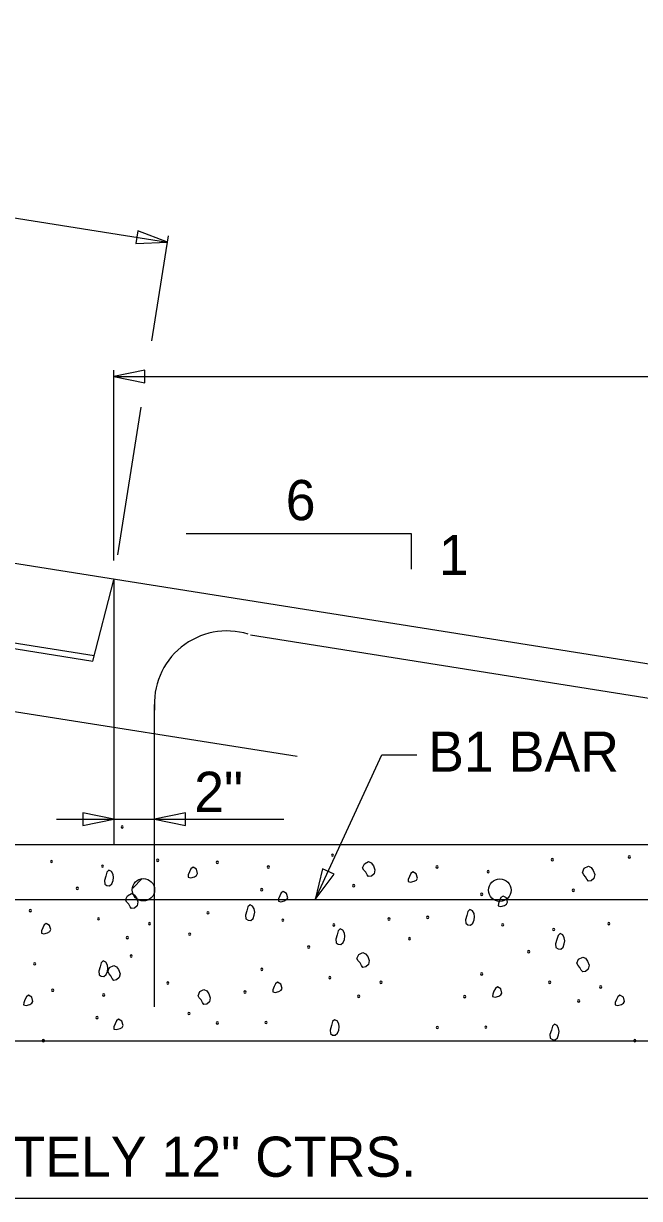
# Model space of a CAD drawing. Extents: x -439.2 to -407.9, y -458.1 to -436.2.
# Drawn here: x -431.521 to -429.218, y -451.117 to -446.728 of the extents above; entities that cross this region are included whole.
import ezdxf

# ---------------------------------------------------------------- set-up
doc = ezdxf.new("R2010")
doc.units = 0
doc.layers.add('Level 4', color=7, linetype='Continuous')
doc.layers.add('Level 45', color=7, linetype='Continuous')

msp = doc.modelspace()

# ---------------------------------------------------------------- linework, layer by layer
at = {"layer": 'Level 4'}
for p, q in [((-436.1395, -446.7284), (-430.9827, -447.5452)), ((-439.1627, -447.54), (-425.6904, -449.6734)), ((-431.0411, -447.9134), (-430.979, -447.5214)), ((-431.1827, -448.7339), (-431.1827, -448.023)), ((-431.1827, -448.0471), (-425.6902, -448.0471)), ((-431.1677, -448.7131), (-431.0803, -448.1614)), ((-436.4193, -448.2716), (-431.2564, -449.0896)), ((-436.4245, -448.2926), (-431.261, -449.11)), ((-436.5705, -448.5037), (-430.4973, -449.4655)), ((-430.9131, -448.6339), (-430.071, -448.6339)), ((-430.071, -448.6339), (-430.071, -448.7672)), ((-431.261, -449.11), (-431.1829, -448.8061)), ((-431.1829, -448.804), (-431.1829, -449.7952)), ((-430.6716, -449.0119), (-426.0033, -449.7521)), ((-431.0317, -449.2723), (-431.0317, -450.401)), ((-430.4303, -450.0011), (-430.1809, -449.4603)), ((-430.1809, -449.4603), (-430.0506, -449.4603)), ((-431.397, -449.7005), (-430.5476, -449.7005)), ((-436.4193, -449.7952), (-425.6904, -449.7952)), ((-431.1122, -449.958), (-431.0767, -449.9225)), ((-436.9348, -450.001), (-431.0317, -450.001)), ((-431.0317, -450.001), (-425.8762, -450.001)), ((-437.1984, -450.5281), (-425.6904, -450.5281)), ((-425.6902, -451.1174), (-437.1989, -451.1174))]:
    msp.add_line(p, q, dxfattribs=at)
for points in [[(-431.1012, -447.5508), (-430.9827, -447.5452), (-431.0937, -447.5032)], [(-431.0666, -448.023), (-431.1827, -448.0471), (-431.0666, -448.0712)], [(-431.2989, -449.7246), (-431.1827, -449.7005), (-431.2989, -449.6764)], [(-430.9153, -449.6764), (-431.0315, -449.7005), (-430.9153, -449.7246)], [(-430.2529, -449.8825), (-430.2463, -449.8668), (-430.2308, -449.8592), (-430.2206, -449.864), (-430.2127, -449.8748), (-430.207, -449.89), (-430.2101, -449.9046), (-430.2201, -449.9135), (-430.2308, -449.915), (-430.2363, -449.9079), (-430.2412, -449.8981), (-430.2482, -449.8905), (-430.2529, -449.8825)], [(-431.2014, -449.891), (-431.2093, -449.8984), (-431.213, -449.913), (-431.2184, -449.9298), (-431.2169, -449.9429), (-431.2087, -449.9485), (-431.1988, -449.9494), (-431.1903, -449.942), (-431.1858, -449.9299), (-431.184, -449.9182), (-431.1858, -449.9066), (-431.1918, -449.8957), (-431.2014, -449.891)], [(-430.8868, -449.8803), (-430.8946, -449.8862), (-430.8998, -449.8972), (-430.9045, -449.9084), (-430.9049, -449.9166), (-430.8955, -449.919), (-430.8816, -449.9154), (-430.8738, -449.9106), (-430.8699, -449.9037), (-430.8741, -449.8877), (-430.8868, -449.8803)], [(-430.4035, -449.8855), (-430.4303, -450.0011), (-430.3597, -449.9057)], [(-430.065, -449.8975), (-430.0727, -449.9034), (-430.0779, -449.9144), (-430.0827, -449.9256), (-430.0831, -449.9339), (-430.0736, -449.9362), (-430.0598, -449.9326), (-430.052, -449.9278), (-430.0481, -449.9209), (-430.0523, -449.9049), (-430.065, -449.8975)], [(-429.4311, -449.8998), (-429.4245, -449.884), (-429.409, -449.8764), (-429.3987, -449.8813), (-429.3909, -449.892), (-429.3851, -449.9072), (-429.3883, -449.9218), (-429.3983, -449.9307), (-429.409, -449.9322), (-429.4145, -449.9252), (-429.4194, -449.9153), (-429.4264, -449.9078), (-429.4311, -449.8998)], [(-431.1388, -450.0021), (-431.1323, -449.9863), (-431.1168, -449.9787), (-431.1065, -449.9836), (-431.0986, -449.9943), (-431.0929, -450.0095), (-431.096, -450.0241), (-431.106, -450.033), (-431.1168, -450.0345), (-431.1222, -450.0275), (-431.1271, -450.0176), (-431.1341, -450.0101), (-431.1388, -450.0021)], [(-430.5497, -449.9703), (-430.5575, -449.9762), (-430.5627, -449.9872), (-430.5675, -449.9984), (-430.5679, -450.0066), (-430.5584, -450.009), (-430.5445, -450.0054), (-430.5368, -450.0006), (-430.5328, -449.9937), (-430.5371, -449.9777), (-430.5497, -449.9703)], [(-429.7279, -449.9875), (-429.7357, -449.9934), (-429.7409, -450.0044), (-429.7456, -450.0156), (-429.7461, -450.0239), (-429.7366, -450.0262), (-429.7227, -450.0226), (-429.7149, -450.0178), (-429.711, -450.0109), (-429.7153, -449.9949), (-429.7279, -449.9875)], [(-430.6736, -450.0204), (-430.6815, -450.0278), (-430.6852, -450.0425), (-430.6905, -450.0593), (-430.6891, -450.0723), (-430.6809, -450.0779), (-430.671, -450.0788), (-430.6625, -450.0714), (-430.658, -450.0593), (-430.6562, -450.0476), (-430.658, -450.036), (-430.664, -450.0252), (-430.6736, -450.0204)], [(-429.8517, -450.0376), (-429.8597, -450.0451), (-429.8634, -450.0597), (-429.8687, -450.0765), (-429.8673, -450.0895), (-429.8591, -450.0951), (-429.8491, -450.096), (-429.8407, -450.0887), (-429.8362, -450.0766), (-429.8343, -450.0648), (-429.8362, -450.0532), (-429.8422, -450.0424), (-429.8517, -450.0376)], [(-431.4356, -450.0898), (-431.4434, -450.0957), (-431.4486, -450.1067), (-431.4534, -450.1179), (-431.4538, -450.1262), (-431.4443, -450.1285), (-431.4305, -450.1249), (-431.4227, -450.1201), (-431.4188, -450.1132), (-431.423, -450.0972), (-431.4356, -450.0898)], [(-430.3365, -450.1104), (-430.3445, -450.1179), (-430.3482, -450.1325), (-430.3535, -450.1493), (-430.3521, -450.1623), (-430.3439, -450.1679), (-430.3339, -450.1688), (-430.3255, -450.1614), (-430.3209, -450.1494), (-430.3191, -450.1376), (-430.3209, -450.126), (-430.327, -450.1152), (-430.3365, -450.1104)], [(-429.5147, -450.1276), (-429.5226, -450.1351), (-429.5264, -450.1497), (-429.5317, -450.1665), (-429.5303, -450.1795), (-429.5221, -450.1851), (-429.5121, -450.186), (-429.5037, -450.1787), (-429.4991, -450.1666), (-429.4973, -450.1548), (-429.4991, -450.1432), (-429.5051, -450.1324), (-429.5147, -450.1276)], [(-430.274, -450.2215), (-430.2674, -450.2058), (-430.2519, -450.1981), (-430.2416, -450.203), (-430.2337, -450.2137), (-430.228, -450.229), (-430.2311, -450.2436), (-430.2412, -450.2524), (-430.2519, -450.254), (-430.2574, -450.2469), (-430.2623, -450.2371), (-430.2693, -450.2295), (-430.274, -450.2215)], [(-429.4522, -450.2387), (-429.4456, -450.223), (-429.4301, -450.2154), (-429.4198, -450.2202), (-429.4119, -450.2309), (-429.4062, -450.2462), (-429.4093, -450.2608), (-429.4194, -450.2696), (-429.4301, -450.2712), (-429.4355, -450.2641), (-429.4405, -450.2543), (-429.4475, -450.2467), (-429.4522, -450.2387)], [(-431.2224, -450.2299), (-431.2304, -450.2374), (-431.2341, -450.252), (-431.2394, -450.2688), (-431.238, -450.2819), (-431.2298, -450.2875), (-431.2198, -450.2883), (-431.2114, -450.281), (-431.2069, -450.2689), (-431.205, -450.2571), (-431.2069, -450.2455), (-431.2129, -450.2347), (-431.2224, -450.2299)], [(-431.2052, -450.2701), (-431.1987, -450.2544), (-431.1832, -450.2468), (-431.1729, -450.2516), (-431.165, -450.2624), (-431.1593, -450.2776), (-431.1624, -450.2922), (-431.1724, -450.3011), (-431.1832, -450.3026), (-431.1886, -450.2955), (-431.1936, -450.2857), (-431.2006, -450.2781), (-431.2052, -450.2701)], [(-430.8682, -450.3601), (-430.8616, -450.3444), (-430.8461, -450.3368), (-430.8358, -450.3416), (-430.828, -450.3524), (-430.8223, -450.3676), (-430.8254, -450.3822), (-430.8354, -450.3911), (-430.8461, -450.3926), (-430.8516, -450.3855), (-430.8565, -450.3757), (-430.8635, -450.3681), (-430.8682, -450.3601)], [(-430.5708, -450.3093), (-430.5786, -450.3152), (-430.5838, -450.3261), (-430.5885, -450.3374), (-430.589, -450.3456), (-430.5795, -450.3479), (-430.5656, -450.3443), (-430.5578, -450.3396), (-430.5539, -450.3326), (-430.5582, -450.3167), (-430.5708, -450.3093)], [(-429.749, -450.3265), (-429.7568, -450.3324), (-429.762, -450.3433), (-429.7667, -450.3546), (-429.7671, -450.3628), (-429.7577, -450.3652), (-429.7438, -450.3615), (-429.736, -450.3568), (-429.7321, -450.3498), (-429.7363, -450.3339), (-429.749, -450.3265)], [(-431.5021, -450.3579), (-431.5098, -450.3638), (-431.515, -450.3748), (-431.5198, -450.386), (-431.5202, -450.3942), (-431.5107, -450.3966), (-431.4969, -450.393), (-431.4891, -450.3882), (-431.4852, -450.3813), (-431.4894, -450.3653), (-431.5021, -450.3579)], [(-429.2909, -450.3577), (-429.2987, -450.3636), (-429.3039, -450.3746), (-429.3086, -450.3858), (-429.3091, -450.394), (-429.2996, -450.3964), (-429.2857, -450.3927), (-429.2779, -450.388), (-429.274, -450.3811), (-429.2783, -450.3651), (-429.2909, -450.3577)], [(-431.165, -450.4479), (-431.1728, -450.4538), (-431.178, -450.4648), (-431.1828, -450.476), (-431.1832, -450.4843), (-431.1737, -450.4866), (-431.1598, -450.483), (-431.1521, -450.4782), (-431.1481, -450.4713), (-431.1524, -450.4553), (-431.165, -450.4479)], [(-430.3576, -450.4494), (-430.3655, -450.4568), (-430.3693, -450.4714), (-430.3746, -450.4882), (-430.3732, -450.5013), (-430.365, -450.5069), (-430.355, -450.5078), (-430.3466, -450.5004), (-430.342, -450.4883), (-430.3402, -450.4766), (-430.342, -450.4649), (-430.348, -450.4541), (-430.3576, -450.4494)], [(-429.5358, -450.4666), (-429.5437, -450.474), (-429.5474, -450.4887), (-429.5527, -450.5054), (-429.5513, -450.5185), (-429.5431, -450.5241), (-429.5332, -450.525), (-429.5247, -450.5176), (-429.5202, -450.5055), (-429.5184, -450.4938), (-429.5202, -450.4822), (-429.5262, -450.4713), (-429.5358, -450.4666)]]:
    msp.add_lwpolyline(points, close=True, dxfattribs=at)
for centre in [(-431.0725, -449.9641), (-429.74, -449.9655)]:
    msp.add_circle(centre, 0.042, dxfattribs=at)
for centre, radius, start, end in [((-430.7602, -449.2687), 0.2712, 72.9091, 185.2347), ((-431.1516, -449.7295), 0.00416, 0, 180), ((-431.1516, -449.7295), 0.00416, 180, 0), ((-431.416, -449.8585), 0.00416, 0, 180), ((-431.416, -449.8585), 0.00416, 180, 0), ((-431.0193, -449.8541), 0.00416, 0, 180), ((-431.0193, -449.8541), 0.00416, 180, 0), ((-430.7963, -449.8618), 0.00416, 0, 180), ((-430.7963, -449.8618), 0.00416, 180, 0), ((-430.3657, -449.8349), 0.00416, 0, 180), ((-430.3657, -449.8349), 0.00416, 180, 0), ((-429.5439, -449.8521), 0.00416, 0, 180), ((-429.5439, -449.8521), 0.00416, 180, 0), ((-429.2562, -449.8415), 0.00416, 0, 180), ((-429.2562, -449.8415), 0.00416, 180, 0), ((-431.2253, -449.876), 0.00416, 0, 180), ((-431.2253, -449.876), 0.00416, 180, 0), ((-430.6055, -449.8794), 0.00416, 0, 180), ((-430.6055, -449.8794), 0.00416, 180, 0), ((-429.9745, -449.879), 0.00416, 0, 180), ((-429.9745, -449.879), 0.00416, 180, 0), ((-429.7837, -449.8966), 0.00416, 0, 180), ((-429.7837, -449.8966), 0.00416, 180, 0), ((-431.3192, -449.9589), 0.00416, 0, 180), ((-430.2867, -449.9489), 0.00416, 0, 180), ((-430.2867, -449.9489), 0.00416, 180, 0), ((-431.3192, -449.9589), 0.00416, 180, 0), ((-430.6301, -449.9639), 0.00416, 0, 180), ((-430.6301, -449.9639), 0.00416, 180, 0), ((-429.8083, -449.9811), 0.00416, 0, 180), ((-429.8083, -449.9811), 0.00416, 180, 0), ((-429.4649, -449.9661), 0.00416, 0, 180), ((-429.4649, -449.9661), 0.00416, 180, 0), ((-431.4946, -450.0421), 0.00416, 0, 180), ((-431.4946, -450.0421), 0.00416, 180, 0), ((-431.2403, -450.0729), 0.00416, 0, 180), ((-431.2403, -450.0729), 0.00416, 180, 0), ((-431.0495, -450.0905), 0.00416, 0, 180), ((-430.8313, -450.0503), 0.00416, 0, 180), ((-430.8313, -450.0503), 0.00416, 180, 0), ((-430.5512, -450.0779), 0.00416, 0, 180), ((-430.5512, -450.0779), 0.00416, 180, 0), ((-430.1544, -450.0735), 0.00416, 0, 180), ((-430.1544, -450.0735), 0.00416, 180, 0), ((-430.0095, -450.0675), 0.00416, 0, 180), ((-430.0095, -450.0675), 0.00416, 180, 0), ((-429.3326, -450.0908), 0.00416, 0, 180), ((-431.0495, -450.0905), 0.00416, 180, 0), ((-430.8994, -450.13), 0.00416, 0, 180), ((-430.8994, -450.13), 0.00416, 180, 0), ((-430.3604, -450.0955), 0.00416, 0, 180), ((-430.3604, -450.0955), 0.00416, 180, 0), ((-429.7294, -450.0951), 0.00416, 0, 180), ((-429.7294, -450.0951), 0.00416, 180, 0), ((-429.5386, -450.1127), 0.00416, 0, 180), ((-429.5386, -450.1127), 0.00416, 180, 0), ((-429.3326, -450.0908), 0.00416, 180, 0), ((-431.1321, -450.1428), 0.00416, 0, 180), ((-431.1321, -450.1428), 0.00416, 180, 0), ((-430.4544, -450.1784), 0.00416, 0, 180), ((-430.0776, -450.1472), 0.00416, 0, 180), ((-430.0776, -450.1472), 0.00416, 180, 0), ((-431.1181, -450.212), 0.00416, 0, 180), ((-431.1181, -450.212), 0.00416, 180, 0), ((-430.4544, -450.1784), 0.00416, 180, 0), ((-429.6325, -450.1956), 0.00416, 0, 180), ((-429.6325, -450.1956), 0.00416, 180, 0), ((-431.4789, -450.2407), 0.00416, 0, 180), ((-431.4789, -450.2407), 0.00416, 180, 0), ((-430.6297, -450.2615), 0.00416, 0, 180), ((-430.6297, -450.2615), 0.00416, 180, 0), ((-430.3754, -450.2924), 0.00416, 0, 180), ((-430.3754, -450.2924), 0.00416, 180, 0), ((-430.1846, -450.3099), 0.00416, 0, 180), ((-429.8079, -450.2788), 0.00416, 0, 180), ((-429.8079, -450.2788), 0.00416, 180, 0), ((-429.5536, -450.3096), 0.00416, 0, 180), ((-431.4116, -450.3394), 0.00416, 0, 180), ((-431.4116, -450.3394), 0.00416, 180, 0), ((-430.981, -450.3125), 0.00416, 0, 180), ((-430.981, -450.3125), 0.00416, 180, 0), ((-430.693, -450.3461), 0.00416, 0, 180), ((-430.693, -450.3461), 0.00416, 180, 0), ((-430.1846, -450.3099), 0.00416, 180, 0), ((-429.5536, -450.3096), 0.00416, 180, 0), ((-429.3628, -450.3271), 0.00416, 0, 180), ((-429.3628, -450.3271), 0.00416, 180, 0), ((-431.2208, -450.357), 0.00416, 0, 180), ((-431.2208, -450.357), 0.00416, 180, 0), ((-430.2673, -450.3622), 0.00416, 0, 180), ((-430.2673, -450.3622), 0.00416, 180, 0), ((-429.8712, -450.3633), 0.00416, 0, 180), ((-429.8712, -450.3633), 0.00416, 180, 0), ((-429.4455, -450.3794), 0.00416, 0, 180), ((-429.4455, -450.3794), 0.00416, 180, 0), ((-431.2454, -450.4415), 0.00416, 0, 180), ((-430.902, -450.4265), 0.00416, 0, 180), ((-430.902, -450.4265), 0.00416, 180, 0), ((-431.2454, -450.4415), 0.00416, 180, 0), ((-430.7958, -450.4615), 0.00416, 0, 180), ((-430.7958, -450.4615), 0.00416, 180, 0), ((-430.6141, -450.4601), 0.00416, 0, 180), ((-430.6141, -450.4601), 0.00416, 180, 0), ((-429.974, -450.4787), 0.00416, 0, 180), ((-429.974, -450.4787), 0.00416, 180, 0), ((-429.7923, -450.4773), 0.00416, 0, 180), ((-429.7923, -450.4773), 0.00416, 180, 0), ((-431.4466, -450.5279), 0.00416, 0, 180), ((-429.2354, -450.5277), 0.00416, 0, 180), ((-431.4466, -450.5279), 0.00416, 180, 0), ((-429.2354, -450.5277), 0.00416, 180, 0)]:
    msp.add_arc(centre, radius, start, end, dxfattribs=at)

# ---------------------------------------------------------------- texts
for s, p in [('6', (-430.5404, -448.5837)), ('1', (-429.9679, -448.7887)), ('B1 BAR', (-430.0081, -449.5233))]:
    msp.add_text(s, height=0.15, dxfattribs=at).set_placement(p)
at = {"layer": 'Level 45'}
for s, p in [('2"', (-430.8827, -449.6733)), ('C BARS AT APPROXIMATELY 12" CTRS.', (-433.8694, -451.0363))]:
    msp.add_text(s, height=0.15, dxfattribs=at).set_placement(p)

doc.saveas('drawing.dxf')
